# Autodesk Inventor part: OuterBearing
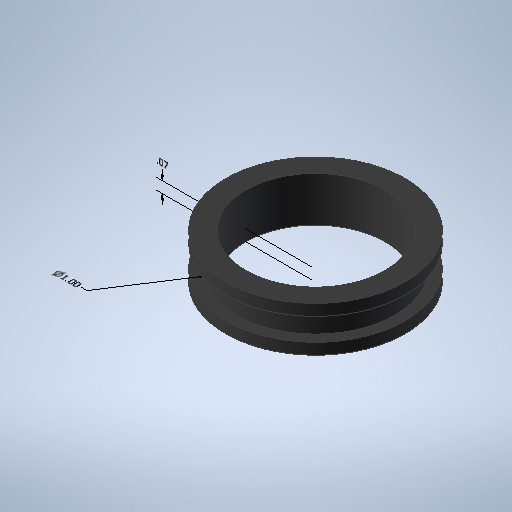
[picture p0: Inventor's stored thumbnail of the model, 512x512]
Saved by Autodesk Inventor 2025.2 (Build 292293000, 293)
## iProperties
Created: 2025-09
Part Number: OuterBearing
Material: Generic
Document SubType Name: Modeling
Designer: tyler
Density: 1 g/cm^3
Appearance: Default
Author: tyler
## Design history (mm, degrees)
node "Annotations"
  node "Linear Dimension 1" dims "d11" = 1.778 (derived)
  node "Diameter Dimension 1" dims "d11" = 1.778 (derived), "d22" = 25.273 (derived)
sketch "Sketch1"
  geometry: C1 r 11.049 at (0, 0); C2 r 14.224 at (0, 0); 1 further point
  constraints: 2 centre point, 2 coincident
  dimensions: "d0" = 22.098 diameter of C1; "d1" = 28.448 diameter of C2
extrude "Extrusion1" new body sketch "Sketch1" distance "d2" = 1.778; taper "d3" = 0 deg
sketch "Sketch2"
  geometry: C1 r 14.224 at (0, 0); C2 r 11.049 at (0, 0); C3 r 12.636 at (0, 0); 1 further point
  constraints: 3 centre point, 3 coincident
  dimensions: "d13" = 25.273 diameter of C3
extrude "Extrusion2" join sketch "Sketch2" distance "d5" = 3.556; taper "d6" = 0 deg
sketch "Sketch5"
  geometry: C1 r 14.224 at (0, 0); 1 further point
  constraints: 1 centre point, 1 coincident
extrude "Extrusion5" join sketch "Sketch5" distance "d14" = 1.778; taper "d15" = 0 deg
sketch "Sketch6"
  geometry: C1 r 11.049 at (0, 0); 1 further point
  constraints: 1 centre point, 1 coincident
  dimensions: "d16" = 22.098 diameter of C1
extrude "Extrusion6" cut sketch "Sketch6" distance "d17" = 25.4; taper "d18" = 0 deg
body "Solid1"
other parameters: "d19" = 13.63781 (derived), "d20" = 2.54746 (derived), "d21" = -4.16965 (derived)
